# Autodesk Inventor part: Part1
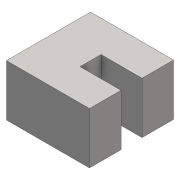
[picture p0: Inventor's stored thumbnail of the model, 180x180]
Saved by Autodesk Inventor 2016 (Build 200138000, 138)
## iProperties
Created: 2015-07
Part Number: Part1
Material: Generic
Document SubType Name: Modeling
Designer: Sandeep
Density: 1 g/cm^3
Appearance: Default
Author: Sandeep
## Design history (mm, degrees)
sketch "Sketch1"
  geometry: L1 (0, 0)-(-30, 0); L2 (-30, 0)-(-30, 40); L3 (-30, 40)-(0, 40); L4 (0, 40)-(0, 0)
  constraints: 8 end point, 2 parallel, 1 horizontal, 1 perpendicular
  dimensions: "d0" = 30 distance between parallel lines of L4 L2; "d1" = 40 distance of L1.end L2.end
extrude "Extrusion1" new body sketch "Sketch1" distance "d2" = 15; taper "d3" = 0 deg
sketch "Sketch2"
  geometry: L1 (0, 40)-(0, 0) reference; L2 (-15, 0)-(-15, 40) reference; L3 (0, 0)-(-15, 0) reference; L4 (-15, 15)-(0, 15); L5 (0, 15)-(0, 25); L6 (0, 25)-(-15, 25); L7 (-15, 25)-(-15, 15)
  constraints: 8 end point, 2 parallel, 2 point on line, 1 horizontal, 1 perpendicular
  dimensions: "d4" = 10 distance between parallel lines of L6 L4; "d5" = 15 distance between parallel lines of L3 L4
extrude "Extrusion2" cut sketch "Sketch2" distance "d6" = 10; taper "d7" = 0 deg
node "Direct Edit2"
body "Solid1"
feature "Size2" dims "d9" = 9.5
